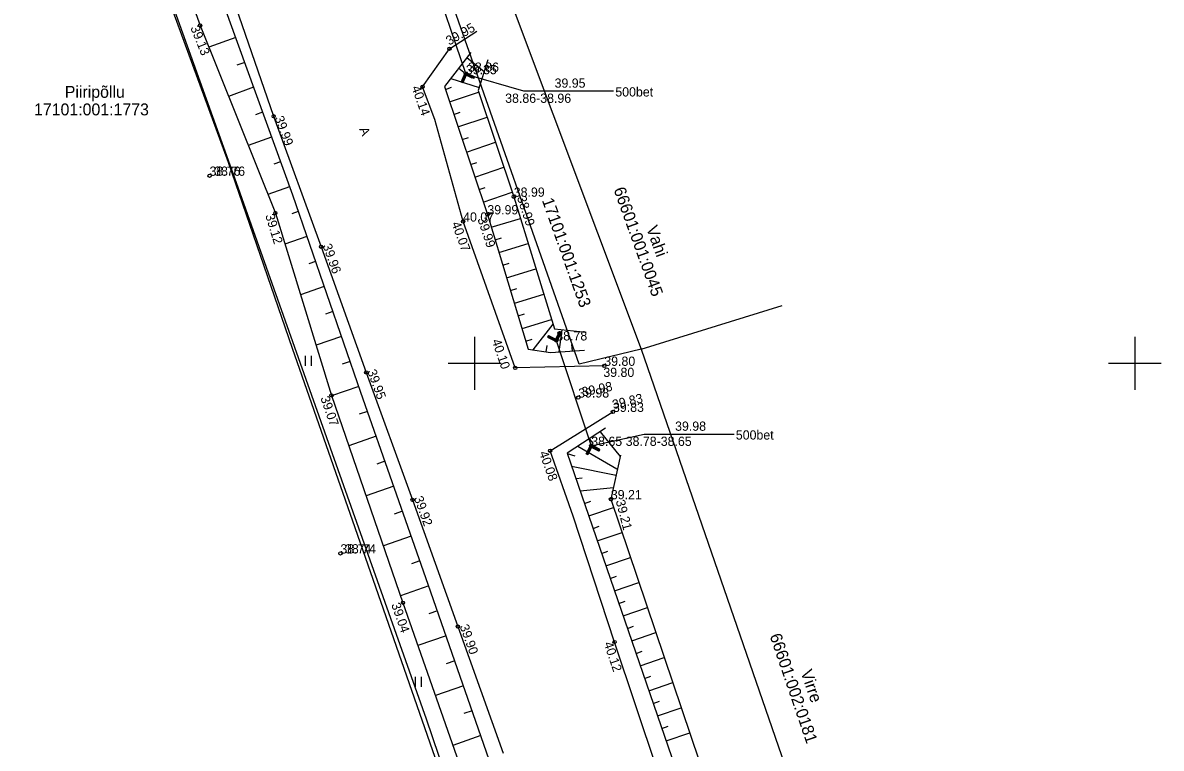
# Model space of a CAD drawing. Extents: x 627548 to 628052, y 6467984 to 6468802.
# Drawn here: x 627915.8 to 628002, y 6468120.9 to 6468175.8 of the extents above; entities that cross this region are included whole.
import ezdxf

# ---------------------------------------------------------------- set-up
doc = ezdxf.new("R2010")
doc.units = 0
for name, color, linetype in [('HALJASTUS', 7, 'Continuous'), ('KORGUS-EH2000', 7, 'Continuous'), ('MOOTKORG-EH2000', 7, 'Continuous'), ('MOOTKORGMUU-EH2000', 7, 'Continuous'), ('MOOTMPUNKT', 7, 'Continuous'), ('PIIR', 7, 'Continuous'), ('RELJEEF', 7, 'Continuous'), ('SITRASS', 7, 'Continuous'), ('TEE', 7, 'Continuous'), ('TRUUP', 7, 'Continuous'), ('VORK', 7, 'Continuous')]:
    doc.layers.add(name, color=color, linetype=linetype)

msp = doc.modelspace()

# ---------------------------------------------------------------- linework, layer by layer
at = {"layer": 'HALJASTUS'}
for p, q in [((627937.173, 6468150.565), (627937.173, 6468149.804)), ((627937.628, 6468150.565), (627937.628, 6468149.804)), ((627945.487, 6468126.266), (627945.487, 6468125.505)), ((627945.942, 6468126.266), (627945.942, 6468125.505))]:
    msp.add_line(p, q, dxfattribs=at)
at = {"layer": 'KORGUS-EH2000'}
for centre in [(627929.207, 6468175.576), (627948.091, 6468173.808), (627946.064, 6468170.933), (627934.781, 6468168.694), (627934.909, 6468161.365), (627938.378, 6468158.823), (627953.072, 6468149.65), (627941.796, 6468149.304), (627939.161, 6468147.561), (627955.717, 6468143.383), (627945.301, 6468139.654), (627944.576, 6468131.872), (627948.73, 6468130.073), (627960.6, 6468128.902)]:
    msp.add_circle(centre, 0.125, dxfattribs=at)
at = {"layer": 'MOOTMPUNKT'}
for centre in [(627949.332, 6468171.907), (627949.339, 6468171.88), (627929.925, 6468164.191), (627952.966, 6468162.603), (627950.966, 6468161.268), (627949.131, 6468160.723), (627956.188, 6468151.726), (627959.821, 6468149.805), (627957.846, 6468147.404), (627960.478, 6468146.317), (627958.832, 6468143.743), (627960.319, 6468139.708), (627939.834, 6468135.603)]:
    msp.add_circle(centre, 0.125, dxfattribs=at)
at = {"layer": 'PIIR'}
for p, q in [((627947.07, 6468192.48), (627962.62, 6468151.07)), ((627921.83, 6468191.92), (627931.94, 6468163.68)), ((627957.93, 6468149.94), (627943.46, 6468191.01)), ((627931.94, 6468163.68), (627946.33, 6468123.08)), ((627962.62, 6468151.07), (627973.283, 6468154.363)), ((627962.62, 6468151.07), (627957.93, 6468149.94)), ((627962.62, 6468151.07), (627980.89, 6468098.21)), ((627946.33, 6468123.08), (627981.87, 6468019.49))]:
    msp.add_line(p, q, dxfattribs=at)
at = {"layer": 'RELJEEF'}
for p, q in [((627931.906, 6468174.649), (627929.874, 6468173.914)), ((627949.415, 6468173.135), (627950.728, 6468172.097)), ((627932.586, 6468172.768), (627931.996, 6468172.555)), ((627948.801, 6468172.345), (627949.196, 6468172.038)), ((627948.188, 6468171.556), (627950.333, 6468170.879)), ((627933.266, 6468170.887), (627931.364, 6468170.199)), ((627947.785, 6468170.731), (627948.259, 6468170.89)), ((627948.103, 6468169.783), (627950.303, 6468170.522)), ((627933.946, 6468169.006), (627933.395, 6468168.807)), ((627948.422, 6468168.835), (627948.896, 6468168.994)), ((627948.741, 6468167.887), (627950.941, 6468168.627)), ((627934.626, 6468167.125), (627932.855, 6468166.485)), ((627949.059, 6468166.939), (627949.533, 6468167.098)), ((627949.378, 6468165.991), (627951.578, 6468166.731)), ((627935.306, 6468165.244), (627934.794, 6468165.059)), ((627949.697, 6468165.043), (627950.171, 6468165.203)), ((627950.015, 6468164.095), (627952.215, 6468164.835)), ((627935.986, 6468163.364), (627934.345, 6468162.77)), ((627950.334, 6468163.148), (627950.808, 6468163.307)), ((627950.653, 6468162.2), (627952.853, 6468162.939)), ((627936.649, 6468161.477), (627936.168, 6468161.31)), ((627950.971, 6468161.252), (627951.449, 6468161.397)), ((627951.262, 6468160.295), (627953.47, 6468160.967)), ((627937.302, 6468159.586), (627935.634, 6468159.01)), ((627951.553, 6468159.338), (627952.032, 6468159.484)), ((627951.844, 6468158.382), (627954.058, 6468159.056)), ((627937.956, 6468157.696), (627937.436, 6468157.517)), ((627952.136, 6468157.425), (627952.614, 6468157.571)), ((627952.427, 6468156.468), (627954.647, 6468157.144)), ((627938.609, 6468155.806), (627936.813, 6468155.185)), ((627952.718, 6468155.512), (627953.196, 6468155.657)), ((627953.009, 6468154.555), (627955.235, 6468155.233)), ((627939.263, 6468153.916), (627938.704, 6468153.723)), ((627953.3, 6468153.598), (627953.779, 6468153.744)), ((627953.592, 6468152.642), (627955.824, 6468153.321)), ((627954.427, 6468151.018), (627955.938, 6468152.951)), ((627956.408, 6468150.854), (627956.629, 6468152.543)), ((627939.916, 6468152.025), (627937.991, 6468151.36)), ((627953.883, 6468151.685), (627954.361, 6468151.831)), ((627955.414, 6468150.857), (627955.494, 6468151.35)), ((627957.405, 6468150.931), (627957.366, 6468151.43)), ((627940.569, 6468150.135), (627939.973, 6468149.929)), ((627941.223, 6468148.245), (627939.17, 6468147.535)), ((627941.883, 6468146.357), (627941.266, 6468146.14)), ((627959.506, 6468144.814), (627961.025, 6468142.944)), ((627942.546, 6468144.47), (627940.478, 6468143.744)), ((627957.829, 6468143.723), (627960.772, 6468142.015)), ((627958.667, 6468144.268), (627958.99, 6468143.926)), ((627957.016, 6468143.169), (627957.6, 6468142.992)), ((627943.209, 6468142.583), (627942.585, 6468142.364)), ((627957.341, 6468142.224), (627960.716, 6468141.526)), ((627957.667, 6468141.278), (627958.141, 6468141.336)), ((627943.871, 6468140.696), (627941.783, 6468139.963)), ((627957.992, 6468140.333), (627960.513, 6468140.597)), ((627958.318, 6468139.387), (627958.79, 6468139.55)), ((627944.534, 6468138.809), (627943.905, 6468138.588)), ((627958.643, 6468138.442), (627960.528, 6468139.09)), ((627958.968, 6468137.496), (627959.441, 6468137.659)), ((627945.197, 6468136.922), (627943.089, 6468136.182)), ((627959.294, 6468136.55), (627961.168, 6468137.195)), ((627959.619, 6468135.605), (627960.092, 6468135.768)), ((627959.945, 6468134.659), (627961.807, 6468135.3)), ((627945.859, 6468135.035), (627945.224, 6468134.812)), ((627960.27, 6468133.714), (627960.743, 6468133.876)), ((627960.596, 6468132.768), (627962.447, 6468133.406)), ((627946.522, 6468133.148), (627944.392, 6468132.406)), ((627960.921, 6468131.823), (627961.394, 6468131.985)), ((627947.18, 6468131.259), (627946.541, 6468131.037)), ((627961.247, 6468130.877), (627963.087, 6468131.511)), ((627961.572, 6468129.931), (627962.045, 6468130.094)), ((627947.837, 6468129.37), (627945.71, 6468128.629)), ((627961.897, 6468128.986), (627963.727, 6468129.616)), ((627962.223, 6468128.04), (627962.696, 6468128.203)), ((627948.495, 6468127.482), (627947.858, 6468127.26)), ((627962.548, 6468127.095), (627964.367, 6468127.721)), ((627949.153, 6468125.593), (627947.03, 6468124.854)), ((627962.874, 6468126.149), (627963.346, 6468126.312)), ((627963.199, 6468125.204), (627965.007, 6468125.826)), ((627963.525, 6468124.258), (627963.997, 6468124.421)), ((627963.85, 6468123.313), (627965.647, 6468123.931)), ((627949.811, 6468123.704), (627949.175, 6468123.483)), ((627964.175, 6468122.367), (627964.648, 6468122.53)), ((627950.469, 6468121.815), (627948.351, 6468121.078)), ((627964.501, 6468121.421), (627966.287, 6468122.036))]:
    msp.add_line(p, q, dxfattribs=at)
for points in [[(627978.291, 6468008.882), (627983.457, 6468013.678), (627984.21, 6468021.024), (627979.575, 6468037.02), (627973.979, 6468054.36), (627968.222, 6468070.605), (627961.466, 6468089.433), (627957.405, 6468099.776), (627954.697, 6468099.952), (627954.601, 6468100.77), (627956.677, 6468103.285), (627952.114, 6468117.091), (627946.482, 6468133.262), (627941.383, 6468147.782), (627936.221, 6468162.714), (627931.414, 6468176.011), (627926.765, 6468189.068), (627921.448, 6468202.325), (627917.805, 6468212.302), (627916.173, 6468214.408), (627912.962, 6468214.481), (627910.459, 6468214.182)], [(627910.966, 6468212.647), (627913.157, 6468213.418), (627915.522, 6468212.557), (627919.56, 6468201.376), (627924.571, 6468188.424), (627929.207, 6468175.576), (627934.909, 6468161.365), (627939.161, 6468147.561), (627944.576, 6468131.872), (627949.813, 6468116.897), (627954.804, 6468102.831), (627953.147, 6468101.408), (627953.982, 6468098.417), (627956.488, 6468098.118), (627959.583, 6468088.974), (627966.658, 6468069.004), (627971.68, 6468054.444), (627977.14, 6468035.885), (627981.189, 6468020.389), (627981.639, 6468013.545), (627978.211, 6468009.476)], [(627949.722, 6468173.53), (627947.713, 6468170.945), (627950.966, 6468161.268), (627954.068, 6468151.076), (627955.745, 6468150.803), (627958.333, 6468151.003)], [(627951.007, 6468172.96), (627950.26, 6468170.652), (627952.966, 6468162.603), (627956.044, 6468152.607), (627958.449, 6468152.346)], [(627959.925, 6468145.086), (627957.009, 6468143.19), (627968.192, 6468110.697), (627973.76, 6468093.308), (627974.813, 6468091.968), (627977.619, 6468091.138)], [(627961.048, 6468143.048), (627960.319, 6468139.708), (627969.706, 6468111.912), (627975.527, 6468093.175), (627977.537, 6468092.509)]]:
    msp.add_lwpolyline(points, dxfattribs=at)
at = {"layer": 'SITRASS'}
msp.add_lwpolyline([(627947.216, 6468119.583), (627940.944, 6468137.544), (627936.199, 6468151.108), (627931.361, 6468165.186), (627924.482, 6468184.013), (627921.137, 6468194.069), (627919.519, 6468197.087), (627916.208, 6468207.498), (627913.328, 6468217.079), (627911.258, 6468222.936), (627909.418, 6468228.846), (627904.458, 6468242.929), (627901.383, 6468250.765), (627898.374, 6468251.727), (627897.323, 6468252.46), (627895.041, 6468257.946), (627892.765, 6468263.751)], dxfattribs=at)
at = {"layer": 'TEE'}
for points in [[(627910.11, 6468214.994), (627913.055, 6468215.115), (627917.929, 6468214.671), (627920.824, 6468207.045), (627924.552, 6468197.415), (627928.058, 6468187.889), (627931.441, 6468178.362), (627934.781, 6468168.694), (627938.378, 6468158.823), (627941.796, 6468149.304), (627945.301, 6468139.654), (627948.73, 6468130.073), (627952.157, 6468120.49)], [(627959.821, 6468149.805), (627953.072, 6468149.65), (627949.131, 6468160.723), (627946.98, 6468168.441), (627946.064, 6468170.933), (627948.091, 6468173.808), (627950.168, 6468175.146)], [(627977.472, 6468089.955), (627975.167, 6468090.332), (627973.79, 6468090.987), (627972.767, 6468093.614), (627970.692, 6468100.023), (627967.147, 6468109.656), (627963.821, 6468119.239), (627960.6, 6468128.902), (627957.471, 6468138.439), (627955.717, 6468143.383), (627960.478, 6468146.317)]]:
    msp.add_lwpolyline(points, dxfattribs=at)
at = {"layer": 'TRUUP'}
for p, q in [((627949.297, 6468172.001), (627948.972, 6468171.294)), ((627949.101, 6468171.235), (627948.972, 6468171.294)), ((627949.01, 6468171.277), (627948.981, 6468171.314)), ((627949.061, 6468171.253), (627948.993, 6468171.339)), ((627949.104, 6468171.24), (627949.004, 6468171.365)), ((627949.115, 6468171.265), (627949.016, 6468171.39)), ((627949.127, 6468171.291), (627949.028, 6468171.415)), ((627949.332, 6468171.907), (627949.037, 6468171.265)), ((627949.139, 6468171.316), (627949.039, 6468171.441)), ((627949.15, 6468171.342), (627949.051, 6468171.466)), ((627949.162, 6468171.367), (627949.063, 6468171.492)), ((627949.174, 6468171.392), (627949.074, 6468171.517)), ((627949.185, 6468171.418), (627949.086, 6468171.543)), ((627949.197, 6468171.443), (627949.098, 6468171.568)), ((627949.367, 6468171.813), (627949.101, 6468171.235)), ((627949.209, 6468171.469), (627949.109, 6468171.593)), ((627949.221, 6468171.494), (627949.121, 6468171.619)), ((627949.232, 6468171.52), (627949.133, 6468171.644)), ((627949.244, 6468171.545), (627949.145, 6468171.67)), ((627949.256, 6468171.571), (627949.156, 6468171.695)), ((627949.267, 6468171.596), (627949.168, 6468171.721)), ((627949.279, 6468171.621), (627949.18, 6468171.746)), ((627949.291, 6468171.647), (627949.191, 6468171.771)), ((627949.302, 6468171.672), (627949.203, 6468171.797)), ((627949.314, 6468171.698), (627949.215, 6468171.822)), ((627949.326, 6468171.723), (627949.226, 6468171.848)), ((627949.337, 6468171.749), (627949.238, 6468171.873)), ((627949.349, 6468171.774), (627949.25, 6468171.899)), ((627949.361, 6468171.799), (627949.262, 6468171.924)), ((627949.391, 6468171.801), (627949.273, 6468171.95)), ((627949.442, 6468171.778), (627949.285, 6468171.975)), ((627950.004, 6468171.676), (627949.297, 6468172.001)), ((627949.492, 6468171.755), (627949.297, 6468172)), ((627949.974, 6468171.612), (627949.332, 6468171.907)), ((627949.543, 6468171.732), (627949.346, 6468171.979)), ((627949.945, 6468171.547), (627949.367, 6468171.813)), ((627949.593, 6468171.709), (627949.396, 6468171.956)), ((627949.644, 6468171.685), (627949.446, 6468171.933)), ((627949.694, 6468171.662), (627949.497, 6468171.91)), ((627949.745, 6468171.639), (627949.547, 6468171.886)), ((627949.795, 6468171.616), (627949.598, 6468171.863)), ((627949.846, 6468171.592), (627949.648, 6468171.84)), ((627949.896, 6468171.569), (627949.699, 6468171.817)), ((627949.945, 6468171.548), (627949.749, 6468171.793)), ((627949.957, 6468171.573), (627949.8, 6468171.77)), ((627949.969, 6468171.599), (627949.85, 6468171.747)), ((627949.98, 6468171.624), (627949.901, 6468171.724)), ((627949.945, 6468171.547), (627950.004, 6468171.676)), ((627949.992, 6468171.65), (627949.951, 6468171.701)), ((627956.155, 6468151.821), (627956.436, 6468152.392)), ((627956.188, 6468151.726), (627956.5, 6468152.361)), ((627956.221, 6468151.631), (627956.564, 6468152.329)), ((627956.396, 6468152.312), (627956.492, 6468152.185)), ((627956.409, 6468152.337), (627956.505, 6468152.21)), ((627956.421, 6468152.362), (627956.517, 6468152.235)), ((627956.433, 6468152.387), (627956.53, 6468152.26)), ((627956.436, 6468152.392), (627956.564, 6468152.329)), ((627956.476, 6468152.372), (627956.542, 6468152.285)), ((627956.526, 6468152.348), (627956.554, 6468152.31)), ((627955.585, 6468152.102), (627955.522, 6468151.974)), ((627955.522, 6468151.974), (627956.221, 6468151.631)), ((627955.535, 6468152), (627955.574, 6468151.948)), ((627955.547, 6468152.025), (627955.624, 6468151.924)), ((627955.553, 6468152.038), (627956.188, 6468151.726)), ((627955.56, 6468152.05), (627955.674, 6468151.899)), ((627955.572, 6468152.076), (627955.724, 6468151.875)), ((627955.584, 6468152.101), (627955.774, 6468151.85)), ((627955.585, 6468152.102), (627956.155, 6468151.821)), ((627955.633, 6468152.078), (627955.824, 6468151.826)), ((627955.683, 6468152.053), (627955.873, 6468151.801)), ((627955.732, 6468152.029), (627955.923, 6468151.777)), ((627955.782, 6468152.005), (627955.973, 6468151.752)), ((627955.832, 6468151.98), (627956.023, 6468151.728)), ((627955.882, 6468151.956), (627956.073, 6468151.703)), ((627955.932, 6468151.931), (627956.123, 6468151.679)), ((627955.982, 6468151.907), (627956.173, 6468151.654)), ((627956.032, 6468151.882), (627956.221, 6468151.632)), ((627956.082, 6468151.858), (627956.233, 6468151.657)), ((627956.131, 6468151.833), (627956.246, 6468151.682)), ((627956.162, 6468151.834), (627956.258, 6468151.707)), ((627956.174, 6468151.859), (627956.27, 6468151.732)), ((627956.187, 6468151.885), (627956.283, 6468151.757)), ((627956.199, 6468151.91), (627956.295, 6468151.783)), ((627956.211, 6468151.935), (627956.307, 6468151.808)), ((627956.224, 6468151.96), (627956.32, 6468151.833)), ((627956.236, 6468151.985), (627956.332, 6468151.858)), ((627956.248, 6468152.01), (627956.344, 6468151.883)), ((627956.261, 6468152.035), (627956.357, 6468151.908)), ((627956.273, 6468152.06), (627956.369, 6468151.933)), ((627956.285, 6468152.086), (627956.381, 6468151.958)), ((627956.298, 6468152.111), (627956.394, 6468151.984)), ((627956.31, 6468152.136), (627956.406, 6468152.009)), ((627956.322, 6468152.161), (627956.418, 6468152.034)), ((627956.335, 6468152.186), (627956.431, 6468152.059)), ((627956.347, 6468152.211), (627956.443, 6468152.084)), ((627956.359, 6468152.236), (627956.455, 6468152.109)), ((627956.372, 6468152.261), (627956.468, 6468152.134)), ((627956.384, 6468152.287), (627956.48, 6468152.159)), ((627958.801, 6468143.839), (627958.447, 6468143.145)), ((627958.832, 6468143.743), (627958.511, 6468143.113)), ((627958.818, 6468143.56), (627958.724, 6468143.688)), ((627958.831, 6468143.584), (627958.737, 6468143.713)), ((627958.844, 6468143.609), (627958.75, 6468143.738)), ((627958.856, 6468143.634), (627958.762, 6468143.763)), ((627958.887, 6468143.635), (627958.775, 6468143.788)), ((627958.936, 6468143.61), (627958.788, 6468143.813)), ((627958.986, 6468143.585), (627958.8, 6468143.838)), ((627959.494, 6468143.485), (627958.801, 6468143.839)), ((627959.462, 6468143.422), (627958.832, 6468143.743)), ((627959.035, 6468143.559), (627958.848, 6468143.815)), ((627959.085, 6468143.534), (627958.898, 6468143.789)), ((627959.134, 6468143.509), (627958.947, 6468143.764)), ((627959.184, 6468143.484), (627958.997, 6468143.739)), ((627959.233, 6468143.458), (627959.046, 6468143.714)), ((627959.283, 6468143.433), (627959.096, 6468143.688)), ((627958.574, 6468143.081), (627958.447, 6468143.145)), ((627958.485, 6468143.126), (627958.457, 6468143.164)), ((627958.534, 6468143.101), (627958.47, 6468143.189)), ((627958.577, 6468143.086), (627958.482, 6468143.214)), ((627958.589, 6468143.111), (627958.495, 6468143.239)), ((627958.602, 6468143.136), (627958.508, 6468143.264)), ((627958.615, 6468143.161), (627958.521, 6468143.289)), ((627958.628, 6468143.185), (627958.533, 6468143.314)), ((627958.64, 6468143.21), (627958.546, 6468143.339)), ((627958.653, 6468143.235), (627958.559, 6468143.364)), ((627958.666, 6468143.26), (627958.571, 6468143.389)), ((627958.863, 6468143.647), (627958.574, 6468143.081)), ((627958.678, 6468143.285), (627958.584, 6468143.414)), ((627958.691, 6468143.31), (627958.597, 6468143.439)), ((627958.704, 6468143.335), (627958.61, 6468143.464)), ((627958.717, 6468143.36), (627958.622, 6468143.489)), ((627958.729, 6468143.385), (627958.635, 6468143.514)), ((627958.742, 6468143.41), (627958.648, 6468143.538)), ((627958.755, 6468143.435), (627958.661, 6468143.563)), ((627958.767, 6468143.46), (627958.673, 6468143.588)), ((627958.78, 6468143.485), (627958.686, 6468143.613)), ((627958.793, 6468143.51), (627958.699, 6468143.638)), ((627958.806, 6468143.535), (627958.711, 6468143.663)), ((627959.43, 6468143.358), (627958.863, 6468143.647)), ((627959.332, 6468143.408), (627959.145, 6468143.663)), ((627959.382, 6468143.383), (627959.195, 6468143.638)), ((627959.43, 6468143.359), (627959.244, 6468143.613)), ((627959.443, 6468143.384), (627959.294, 6468143.587)), ((627959.455, 6468143.409), (627959.343, 6468143.562)), ((627959.468, 6468143.434), (627959.393, 6468143.537)), ((627959.43, 6468143.358), (627959.494, 6468143.485)), ((627959.481, 6468143.459), (627959.442, 6468143.512))]:
    msp.add_line(p, q, dxfattribs=at)
for points in [[(627946.63, 6468179.82), (627949.339, 6468171.88)], [(627949.339, 6468171.88), (627953.71, 6468170.613), (627960.519, 6468170.613)], [(627956.188, 6468151.726), (627958.832, 6468143.743)], [(627958.832, 6468143.743), (627962.838, 6468144.646), (627969.647, 6468144.646)]]:
    msp.add_lwpolyline(points, dxfattribs=at)
at = {"layer": 'VORK'}
for p, q in [((627950, 6468152), (627950, 6468148)), ((628000, 6468152), (628000, 6468148)), ((627948, 6468150), (627952, 6468150)), ((627998, 6468150), (628002, 6468150))]:
    msp.add_line(p, q, dxfattribs=at)

# ---------------------------------------------------------------- texts
at = {"layer": 'KORGUS-EH2000'}
for s, rotation, p in [(' 39.95', 29.65639, (627947.846, 6468173.911)), (' 39.13', 291.86256, (627928.363, 6468175.64)), (' 40.14', 289.50608, (627945.125, 6468171.118)), (' 39.99', 290.02178, (627934.754, 6468168.829)), ('38.99', 288.18409, (627953.2, 6468162.542)), (' 39.12', 287.12023, (627934.058, 6468161.441)), ('39.99', 288.27898, (627950.211, 6468160.909)), ('40.07', 290.36437, (627948.237, 6468160.578)), (' 39.96', 289.75176, (627938.387, 6468159.157)), (' 40.10', 288.83793, (627951.211, 6468151.948)), (' 39.95', 289.96165, (627941.772, 6468149.641)), ('39.98', 11.31615, (627958.189, 6468147.476)), (' 39.07', 289.04192, (627938.228, 6468147.624)), ('39.83', 13.05274, (627960.513, 6468146.517)), (' 40.08', 289.53333, (627954.788, 6468143.468)), (' 39.92', 289.69208, (627945.31, 6468140.052)), ('39.21', 284.51002, (627960.684, 6468139.578)), (' 39.04', 289.27556, (627943.588, 6468131.985)), (' 39.90', 289.67768, (627948.772, 6468130.341)), (' 40.12', 288.43495, (627959.694, 6468129.045))]:
    msp.add_text(s, height=0.7, rotation=rotation, dxfattribs=at).set_placement(p)
for s, p in [('38.76', (627930.275, 6468164.191)), ('39.80', (627959.749, 6468148.964)), ('38.74', (627940.184, 6468135.603))]:
    msp.add_text(s, height=0.7, dxfattribs=at).set_placement(p)
at = {"layer": 'MOOTKORG-EH2000'}
for s, p in [('38.86', (627949.499, 6468172.061)), ('38.76', (627929.925, 6468164.191)), ('38.99', (627952.966, 6468162.603)), ('39.99', (627950.966, 6468161.268)), ('40.07', (627949.131, 6468160.723)), ('38.78', (627956.188, 6468151.726)), ('39.80', (627959.821, 6468149.805)), ('39.98', (627957.846, 6468147.404)), ('39.83', (627960.478, 6468146.317)), ('38.65', (627958.832, 6468143.743)), ('39.21', (627960.319, 6468139.708)), ('38.74', (627939.834, 6468135.603))]:
    msp.add_text(s, height=0.7, dxfattribs=at).set_placement(p)
at = {"layer": 'MOOTKORGMUU-EH2000'}
msp.add_text('39.35', height=0.7, dxfattribs=at).set_placement((627949.339, 6468171.88))
at = {"layer": 'PIIR'}
for s, p in [('Piiripõllu', (627918.962, 6468170.095)), ('17101:001:1773', (627916.632, 6468168.764))]:
    msp.add_text(s, height=0.9, dxfattribs=at).set_placement(p)
for s, rotation, p in [('66601:001:0045', 289.80362, (627960.514, 6468163.155)), ('17101:001:1253', 289.56788, (627955.086, 6468162.342)), ('Vahi', 289.80362, (627962.982, 6468160.231)), ('66601:002:0181', 288.89125, (627972.333, 6468129.377)), ('Virre', 288.89125, (627974.68, 6468126.63))]:
    msp.add_text(s, height=0.9, rotation=rotation, dxfattribs=at).set_placement(p)
at = {"layer": 'TEE'}
msp.add_text('A', height=0.7, rotation=292.11557, dxfattribs=at).set_placement((627941.255, 6468167.723))
at = {"layer": 'TRUUP'}
for s, p in [(' 39.95', (627955.796, 6468170.857)), (' 38.86-38.96', (627952.055, 6468169.712)), ('500bet', (627960.656, 6468170.192)), (' 39.98', (627964.924, 6468144.89)), ('500bet', (627969.784, 6468144.225)), (' 38.78-38.65', (627961.183, 6468143.745))]:
    msp.add_text(s, height=0.7, dxfattribs=at).set_placement(p)

doc.saveas('drawing.dxf')
